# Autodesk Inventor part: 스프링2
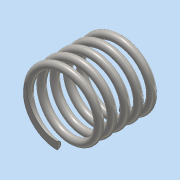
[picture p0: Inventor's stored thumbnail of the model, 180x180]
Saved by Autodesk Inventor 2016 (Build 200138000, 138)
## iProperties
Created: 2019-11
Part Number: 스프링2
Material: 스테인레스 스틸
Document SubType Name: Modeling
Designer: user
Density: 8 g/cm^3
Appearance: 반연마
Mass: 6.55014 g
Surface Area: 16.6978 cm^2
Volume: 0.818768 cm^3
Author: user
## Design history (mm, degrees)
sketch "스케치1"
  geometry: L1 (0, 0)-(17.5, 0); L2 (17.5, 0)-(17.5, -8.5); L3 (17.5, -8.5)-(0, -8.5); L4 (0, -8.5)-(0, 0); C1 r 1 at (0, -8.5)
  constraints: 8 end point, 2 parallel, 1 centre point, 1 coincident, 1 horizontal, 1 perpendicular
  dimensions: "d0" = 17.5 distance of L1.start L1.end (derived); "d1" = 17 diameter of L3 L1; "d2" = 2 diameter of C1
feature "코일1" sketch "스케치1" pitch "d3" = 10; turns "d5" = 5; dims "d4" = 17.5 (= d0), "d6" = 0, angle "d7" = 90 deg, angle "d8" = 90 deg, "d9" = 0, "d10" = 0
sketch "스케치2"
  geometry: L1 (-15.996, 0)-(15.996, 0); L2 (15.996, 0)-(15.996, 17.5); L3 (15.996, 17.5)-(-15.996, 17.5); L4 (-15.996, 17.5)-(-15.996, 0); 2 further points
  constraints: 8 end point, 2 parallel, 1 coincident, 1 horizontal, 1 midpoint, 1 perpendicular
  dimensions: "d12" = 31.99189 distance between parallel lines of L2 L4; "d13" = 17.5 distance of L1.end L2.end (= d0)
extrude "돌출1" sketch "스케치2" stored distance "d14" = 38.25; taper "d15" = 0 deg
node "솔리드1"
